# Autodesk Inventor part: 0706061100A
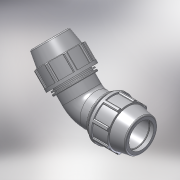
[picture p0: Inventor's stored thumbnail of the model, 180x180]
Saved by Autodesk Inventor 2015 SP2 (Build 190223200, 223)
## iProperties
Created: 2017-02
Part Number: 0706061100A
Material: PVC-Piping
Description: PLASSON 45° ELBOW 110-110
Document SubType Name: Modeling
Designer: KIM
Mass: 92.6774 g
Surface Area: 199.44 cm^2
Volume: 66.1981 cm^3
Density: 1.4 g/cm^3
Appearance: Smooth - White
Author: Кирилл
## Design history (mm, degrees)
derived "87060.ipt"
feature "Solid1::87060.ipt"
tag "TaggingFeature1"
body "Solid1"
other parameters: "d4" = 19.58333, "d5" = 58.75, "d7" = 181, "d9" = 33.57143, "d11" = 7.83333, "d13" = 120 deg, "d14" = 143, "d15" = 10 deg, "d16" = 157.47, "d18" = 5.5, "d19" = 35 deg, "d20" = 17.5 deg, "d21" = 168.33, "d23" = 0, "d25" = 360 deg, "d27" = 3.62, "d33" = 2.2, "d42" = 79.9, "d43" = 5.43, "d46" = 2.2, "d51" = 235, "d59" = 135 deg, "d63" = 194, "d64" = 99, "d67" = 135.75, "d68" = 14.1, "d70" = 45 deg, "d72" = 12.06667, "d73" = 0, "d75" = 135 deg, "d77" = 154.3206, "d78" = 4.7, "E_" = 181, "A_" = 235, "l_" = 194
